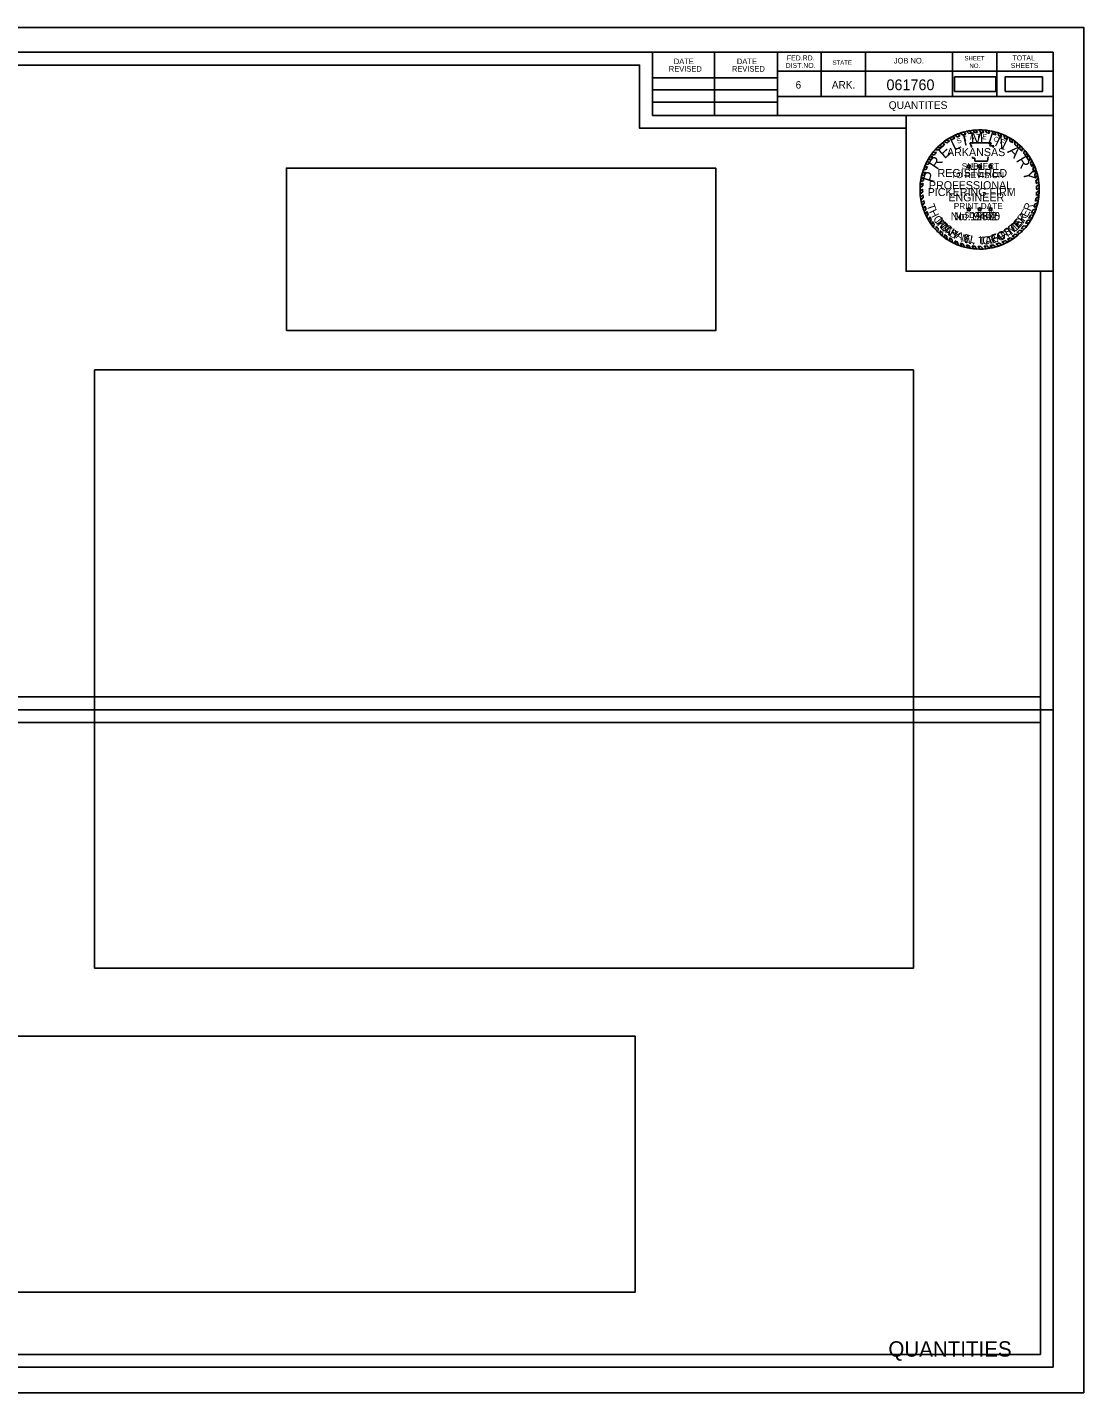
# Model space of a CAD drawing. Extents: x 365 to 1553, y -4 to 209.
# Drawn here: x 907 to 1072.1, y -4 to 209.4 of the extents above; entities that cross this region are included whole.
import ezdxf

# ---------------------------------------------------------------- set-up
doc = ezdxf.new("R2010")
doc.units = 0
for name, color, linetype in [('Default', 7, 'Continuous'), ('R_Border', 7, 'Continuous'), ('R_Border Notes', 7, 'Continuous'), ('R_Border Plan-Plan', 7, 'Continuous'), ('R_Border Title', 7, 'Continuous'), ('R_No Plot', 7, 'Continuous'), ('STAMP_PE_CRAFTON', 7, 'Continuous'), ('STAMP_PE_FOSTER', 7, 'Continuous'), ('STAMP_PE_SEAL-INFO', 7, 'Continuous'), ('STAMP_PE_TAEGTMEYER', 7, 'Continuous'), ('STAMP_PE_TXT', 7, 'Continuous'), ('STAMP_PRELIMINARY', 7, 'Continuous')]:
    doc.layers.add(name, color=color, linetype=linetype)

msp = doc.modelspace()

# ---------------------------------------------------------------- linework, layer by layer
at = {"layer": 'Default'}
for points in [[(1051.92, 199.3), (1058.36, 199.3), (1058.36, 201.61), (1051.92, 201.61)], [(1059.83, 199.3), (1065.66, 199.3), (1065.66, 201.61), (1059.83, 201.61)], [(947.52, 161.96), (1014.61, 161.96), (1014.61, 187.36), (947.52, 187.36)], [(917.53, 62.36), (1045.5, 62.36), (1045.5, 155.81), (917.53, 155.81)], [(810.62, 11.73), (1002.02, 11.73), (1002.02, 51.71), (810.62, 51.71)]]:
    msp.add_lwpolyline(points, close=True, dxfattribs=at)
at = {"layer": 'R_Border'}
for p, q in [((751.17, 205.46), (1067.35, 205.46)), ((1004.71, 195.58), (1004.71, 205.46)), ((1014.39, 195.58), (1014.39, 205.46)), ((1024.25, 205.46), (1024.25, 195.58)), ((1031.09, 205.46), (1031.09, 198.52)), ((1038.03, 205.46), (1038.03, 198.52)), ((1051.61, 205.46), (1051.61, 198.52)), ((1058.55, 205.46), (1058.55, 198.52)), ((1067.35, 0), (1067.35, 205.46)), ((1004.71, 201.44), (1024.25, 201.44)), ((1067.35, 202.52), (1024.25, 202.52)), ((1067.35, 202.54), (1067.35, 202.54)), ((1004.71, 199.58), (1024.25, 199.58)), ((1067.35, 198.52), (1024.25, 198.52)), ((1027.21, 198.52), (1067.35, 198.52)), ((1004.71, 197.64), (1024.25, 197.64)), ((1067.35, 195.58), (1004.71, 195.58)), ((1067.35, 0), (751.17, 0))]:
    msp.add_line(p, q, dxfattribs=at)
at = {"layer": 'R_Border Plan-Plan'}
msp.add_line((751.17, 102.73), (1067.35, 102.73), dxfattribs=at)
at = {"layer": 'R_No Plot'}
for points in [[(738.77, 209.35), (1072.11, 209.35), (1072.11, -3.98), (738.77, -3.98)], [(1065.35, 104.73), (753.17, 104.73), (753.17, 203.46), (1002.71, 203.46), (1002.71, 193.58), (1020.25, 193.58), (1044.35, 193.58), (1044.35, 171.25), (1065.35, 171.25)], [(753.17, 203.46), (1002.71, 203.46), (1002.71, 193.58), (1020.25, 193.58), (1044.35, 193.58), (1044.35, 171.25), (1065.35, 171.25), (1065.35, 2), (753.17, 2)], [(1044.35, 195.58), (1067.35, 195.58), (1067.35, 171.25), (1044.35, 171.25)], [(753.17, 100.73), (1065.35, 100.73), (1065.35, 2), (753.17, 2)]]:
    msp.add_lwpolyline(points, close=True, dxfattribs=at)
at = {"layer": 'STAMP_PE_SEAL-INFO'}
for p, q in [((1051.08, 192.03), (1051.51, 191.81)), ((1051.53, 192.28), (1051.99, 192.06)), ((1051.96, 192.49), (1052.35, 192.22)), ((1052.47, 192.71), (1052.76, 192.38)), ((1052.81, 192.84), (1053.19, 192.53)), ((1053.4, 193.02), (1053.69, 192.67)), ((1053.79, 193.11), (1054.15, 192.77)), ((1054.27, 193.21), (1054.57, 192.84)), ((1054.79, 193.28), (1055.07, 192.9)), ((1055.53, 192.93), (1055.21, 193.32)), ((1056.02, 192.93), (1055.75, 193.34)), ((1056.48, 192.91), (1056.22, 193.34)), ((1056.99, 192.86), (1056.7, 193.31)), ((1057.41, 192.8), (1057.16, 193.25)), ((1057.98, 192.68), (1057.8, 193.14)), ((1058.38, 192.57), (1058.22, 193.04)), ((1058.83, 192.42), (1058.69, 192.9)), ((1059.25, 192.26), (1059.1, 192.76)), ((1059.71, 192.06), (1059.61, 192.56)), ((1060.15, 191.83), (1060.07, 192.34)), ((1060.54, 191.6), (1060.5, 192.1)), ((1048.89, 190.22), (1049.41, 190.19)), ((1049.22, 190.57), (1049.76, 190.53)), ((1049.55, 190.89), (1050.01, 190.75)), ((1049.9, 191.19), (1050.42, 191.09)), ((1050.27, 191.52), (1050.73, 191.31)), ((1050.69, 191.79), (1051.13, 191.58)), ((1054.33, 191.31), (1057.67, 191.31)), ((1054.45, 191.01), (1054.33, 191.31)), ((1054.55, 190.71), (1054.45, 191.01)), ((1054.56, 190.59), (1054.55, 190.71)), ((1057.67, 191.31), (1057.45, 190.82)), ((1057.45, 190.82), (1058.08, 190.82)), ((1058.08, 190.82), (1057.93, 190.59)), ((1060.98, 191.32), (1060.95, 191.83)), ((1061.34, 191.05), (1061.37, 191.54)), ((1061.78, 190.68), (1061.8, 191.2)), ((1062.1, 190.39), (1062.17, 190.88)), ((1062.46, 190.01), (1062.52, 190.54)), ((1062.73, 189.7), (1062.87, 190.17)), ((1047.37, 187.89), (1047.87, 187.99)), ((1047.56, 188.27), (1048.06, 188.34)), ((1047.79, 188.7), (1048.28, 188.72)), ((1048.03, 189.1), (1048.55, 189.13)), ((1048.27, 189.44), (1048.77, 189.44)), ((1048.55, 189.81), (1049.1, 189.83)), ((1054.75, 188.89), (1054.72, 189.1)), ((1055.07, 188.89), (1054.75, 188.89)), ((1055.07, 188.46), (1055.07, 188.89)), ((1057.09, 188.46), (1055.07, 188.46)), ((1057.11, 188.79), (1057.09, 188.46)), ((1057.19, 189.1), (1057.11, 188.79)), ((1063.05, 189.28), (1063.19, 189.78)), ((1063.27, 188.96), (1063.45, 189.43)), ((1063.58, 188.47), (1063.76, 188.96)), ((1063.78, 188.1), (1064.01, 188.54)), ((1064.01, 187.62), (1064.24, 188.1)), ((1047.14, 185.89), (1046.67, 185.64)), ((1046.77, 186.14), (1047.24, 186.33)), ((1046.88, 186.54), (1047.36, 186.71)), ((1047.04, 187.05), (1047.52, 187.18)), ((1047.19, 187.45), (1047.69, 187.6)), ((1064.15, 187.28), (1064.42, 187.71)), ((1064.35, 186.73), (1064.62, 187.2)), ((1064.45, 186.37), (1064.75, 186.82)), ((1064.59, 185.81), (1064.91, 186.25)), ((1064.66, 185.43), (1065.01, 185.78)), ((1046.96, 184.57), (1046.54, 184.31)), ((1046.94, 184.08), (1046.54, 183.74)), ((1046.99, 185), (1046.56, 184.71)), ((1046.95, 183.67), (1046.56, 183.35)), ((1047.05, 185.43), (1046.61, 185.21)), ((1064.72, 184.92), (1065.1, 185.25)), ((1064.75, 184.5), (1065.15, 184.79)), ((1064.76, 183.58), (1065.18, 183.85)), ((1064.77, 183.98), (1065.17, 184.3)), ((1046.98, 183.18), (1046.61, 182.82)), ((1047.03, 182.75), (1046.68, 182.37)), ((1047.11, 182.29), (1046.77, 181.92)), ((1047.2, 181.87), (1046.89, 181.45)), ((1047.33, 181.42), (1047.03, 181)), ((1064.32, 181.24), (1064.81, 181.44)), ((1064.47, 181.73), (1064.94, 181.93)), ((1064.58, 182.18), (1065.03, 182.38)), ((1064.67, 182.68), (1065.11, 182.9)), ((1064.72, 183.07), (1065.15, 183.33)), ((1047.47, 181), (1047.19, 180.59)), ((1047.64, 180.57), (1047.37, 180.15)), ((1047.81, 180.19), (1047.58, 179.73)), ((1048.04, 179.73), (1047.85, 179.24)), ((1048.28, 179.33), (1048.09, 178.86)), ((1063.37, 179.23), (1063.84, 179.22)), ((1063.54, 179.51), (1064.04, 179.56)), ((1063.81, 180), (1064.3, 180.07)), ((1063.97, 180.34), (1064.46, 180.44)), ((1064.19, 180.86), (1064.67, 180.99)), ((1048.48, 179.01), (1048.37, 178.46)), ((1048.76, 178.62), (1048.66, 178.09)), ((1049.07, 178.25), (1048.98, 177.73)), ((1049.37, 177.91), (1049.31, 177.39)), ((1049.69, 177.58), (1049.66, 177.05)), ((1050.03, 177.27), (1050.03, 176.74)), ((1061.68, 177.27), (1062.15, 177.14)), ((1062.08, 177.64), (1062.52, 177.51)), ((1062.34, 177.9), (1062.81, 177.82)), ((1062.72, 178.34), (1063.18, 178.26)), ((1063.03, 178.73), (1063.53, 178.73)), ((1050.39, 176.98), (1050.41, 176.45)), ((1050.73, 176.73), (1050.77, 176.21)), ((1051.16, 176.45), (1051.22, 175.93)), ((1051.51, 176.24), (1051.6, 175.73)), ((1051.99, 175.99), (1052.15, 175.47)), ((1052.36, 175.82), (1052.54, 175.31)), ((1052.86, 175.63), (1053.07, 175.13)), ((1053.27, 175.49), (1053.49, 175)), ((1053.77, 175.36), (1053.99, 174.89)), ((1054.17, 175.27), (1054.42, 174.81)), ((1054.67, 175.19), (1054.91, 174.75)), ((1055.11, 175.14), (1055.38, 174.71)), ((1055.59, 175.11), (1055.9, 174.7)), ((1056.05, 175.11), (1056.4, 174.72)), ((1056.57, 175.14), (1056.9, 174.76)), ((1057.01, 175.18), (1057.38, 174.83)), ((1057.45, 175.25), (1057.84, 174.91)), ((1057.95, 175.36), (1058.33, 175.03)), ((1058.41, 175.48), (1058.82, 175.19)), ((1058.9, 175.65), (1059.34, 175.38)), ((1059.32, 175.81), (1059.74, 175.55)), ((1059.78, 176.02), (1060.26, 175.81)), ((1060.19, 176.23), (1060.6, 176)), ((1060.6, 176.48), (1061.05, 176.28)), ((1060.94, 176.71), (1061.38, 176.52)), ((1061.4, 177.05), (1061.87, 176.9))]:
    msp.add_line(p, q, dxfattribs=at)
for radius, start, end in [(9.32, 117.6544, 120.8099), (8.91, 115.6869, 119.1583), (9.32, 111.3124, 114.7026), (8.91, 110.3086, 113.1659), (9.32, 105.2339, 109.0352), (8.91, 104.0352, 107.3615), (9.32, 99.7525, 102.7765), (8.91, 98.258, 101.0329), (9.32, 93.9381, 96.5517), (8.91, 92.1102, 95.0367), (9.32, 87.7298, 90.6707), (8.91, 85.9628, 88.9097), (9.32, 81.9732, 84.8236), (8.91, 79.9264, 82.696), (9.32, 75.3125, 77.9426), (8.91, 73.5575, 76.2314), (9.32, 69.6061, 72.3058), (8.91, 67.6248, 70.504), (9.32, 63.1329, 66.2704), (8.91, 61.1558, 64.3784), (9.32, 56.9003, 60.0942), (9.32, 135.4021, 138.3031), (8.91, 133.1331, 136.2562), (9.32, 129.7326, 132.5376), (8.91, 127.5297, 130.9683), (9.32, 123.6199, 126.5906), (8.91, 121.9746, 125.11), (8.91, 54.9238, 58.2702), (8.91, 48.3016, 52.0395), (9.32, 50.3492, 53.7159), (8.91, 42.2212, 45.5512), (9.32, 44.3405, 47.3929), (9.32, 38.1247, 41.2316), (9.32, 152.864, 155.5189), (9.32, 147.0072, 149.899), (8.91, 151.0315, 153.573), (9.32, 141.6056, 144.4486), (8.91, 145.0197, 148.2104), (8.91, 139.301, 142.5873), (8.91, 36.135, 39.5311), (8.91, 29.9032, 33.6645), (9.32, 31.9614, 35.4294), (8.91, 23.7732, 27.2211), (9.32, 25.9391, 29.0125), (9.32, 170.0003, 172.6878), (9.32, 164.3068, 166.894), (9.32, 158.4077, 161.0701), (8.91, 167.9048, 170.9039), (8.91, 162.4331, 165.0013), (8.91, 156.3402, 159.2319), (8.91, 17.6802, 21.4251), (9.32, 19.9538, 23.3141), (8.91, 11.5444, 15.2364), (9.32, 13.8421, 17.4447), (9.32, 7.5852, 10.8621), (9.32, 175.7409, 178.2066), (9.32, 181.7251, 184.1626), (8.91, 179.6454, 182.2633), (8.91, 173.73, 176.4734), (8.91, 5.7599, 9.0606), (8.91, 353.8632, 357.1274), (8.91, 359.7329, 3.0639), (9.32, 1.7215, 4.7268), (9.32, 355.7156, 358.9569), (9.32, 187.4204, 190.1927), (9.32, 193.0369, 195.9973), (8.91, 185.4539, 188.234), (8.91, 191.2274, 193.9858), (8.91, 196.9675, 199.8353), (8.91, 341.777, 345.0925), (8.91, 348.0778, 351.3435), (9.32, 343.8925, 347.035), (9.32, 349.8305, 353.0885), (9.32, 198.8967, 201.6281), (9.32, 204.5479, 207.4328), (8.91, 202.7761, 205.4791), (9.32, 210.8636, 213.6571), (8.91, 208.7883, 211.7934), (8.91, 323.5851, 327.4407), (9.32, 325.4405, 328.9872), (8.91, 329.5549, 333.2076), (8.91, 335.6038, 339.1858), (9.32, 331.4037, 334.9332), (9.32, 337.3837, 340.9933), (9.32, 216.6115, 219.491), (8.91, 214.1838, 217.2747), (9.32, 222.48, 225.3801), (8.91, 220.3909, 223.3056), (8.91, 226.2494, 229.2407), (8.91, 310.7744, 314.3161), (9.32, 312.4518, 315.6633), (8.91, 316.6531, 320.3711), (9.32, 318.2846, 321.8043), (9.32, 228.3665, 231.348), (8.91, 232.229, 234.9336), (9.32, 234.295, 236.9452), (8.91, 238.2223, 240.8353), (9.32, 240.1977, 242.8613), (8.91, 244.3204, 246.9486), (9.32, 246.576, 249.1558), (8.91, 250.3491, 253.1216), (9.32, 252.5967, 255.3252), (8.91, 256.505, 259.1192), (8.91, 262.3783, 265.2012), (8.91, 268.3215, 271.277), (8.91, 274.6157, 277.4486), (8.91, 280.3459, 283.5814), (9.32, 282.3199, 285.3702), (8.91, 286.6423, 289.9783), (9.32, 288.5709, 291.9733), (8.91, 292.8745, 296.1185), (9.32, 294.6481, 298.2166), (8.91, 299.0768, 302.1724), (9.32, 300.621, 303.8703), (8.91, 304.823, 308.5143), (9.32, 306.3721, 310.208), (9.32, 258.4433, 261.1398), (9.32, 264.1978, 267.1009), (9.32, 270.2548, 273.3361), (9.32, 276.4239, 279.4357)]:
    msp.add_arc((1055.85, 184.02), radius, start, end, dxfattribs=at)
at = {"layer": 'STAMP_PE_TXT'}
for p, q in [((1054.03, 187.59), (1053.84, 187.74)), ((1053.84, 187.74), (1054.08, 187.74)), ((1054.08, 187.74), (1054.16, 187.97)), ((1054.16, 187.97), (1054.23, 187.74)), ((1054.23, 187.74), (1054.48, 187.74)), ((1054.48, 187.74), (1054.28, 187.59)), ((1055.73, 187.59), (1055.53, 187.74)), ((1055.53, 187.74), (1055.78, 187.74)), ((1055.78, 187.74), (1055.85, 187.97)), ((1055.85, 187.97), (1055.93, 187.74)), ((1055.93, 187.74), (1056.18, 187.74)), ((1056.18, 187.74), (1055.98, 187.59)), ((1057.43, 187.59), (1057.23, 187.74)), ((1057.23, 187.74), (1057.48, 187.74)), ((1057.48, 187.74), (1057.55, 187.97)), ((1057.55, 187.97), (1057.63, 187.74)), ((1057.63, 187.74), (1057.87, 187.74)), ((1057.87, 187.74), (1057.67, 187.59)), ((1053.96, 187.36), (1054.03, 187.59)), ((1054.16, 187.5), (1053.96, 187.36)), ((1054.35, 187.36), (1054.16, 187.5)), ((1054.28, 187.59), (1054.35, 187.36)), ((1055.66, 187.36), (1055.73, 187.59)), ((1055.85, 187.5), (1055.66, 187.36)), ((1056.05, 187.36), (1055.85, 187.5)), ((1055.98, 187.59), (1056.05, 187.36)), ((1057.35, 187.36), (1057.43, 187.59)), ((1057.55, 187.5), (1057.35, 187.36)), ((1057.75, 187.36), (1057.55, 187.5)), ((1057.67, 187.59), (1057.75, 187.36)), ((1054.03, 180.89), (1053.84, 181.03)), ((1053.84, 181.03), (1054.08, 181.03)), ((1053.96, 180.65), (1054.03, 180.89)), ((1054.16, 180.8), (1053.96, 180.65)), ((1054.08, 181.03), (1054.16, 181.26)), ((1054.16, 181.26), (1054.23, 181.03)), ((1054.35, 180.65), (1054.16, 180.8)), ((1054.23, 181.03), (1054.48, 181.03)), ((1054.48, 181.03), (1054.28, 180.89)), ((1054.28, 180.89), (1054.35, 180.65)), ((1055.73, 180.89), (1055.53, 181.03)), ((1055.53, 181.03), (1055.78, 181.03)), ((1055.66, 180.65), (1055.73, 180.89)), ((1055.85, 180.8), (1055.66, 180.65)), ((1055.78, 181.03), (1055.85, 181.26)), ((1055.85, 181.26), (1055.93, 181.03)), ((1056.05, 180.65), (1055.85, 180.8)), ((1055.93, 181.03), (1056.18, 181.03)), ((1056.18, 181.03), (1055.98, 180.89)), ((1055.98, 180.89), (1056.05, 180.65)), ((1057.43, 180.89), (1057.23, 181.03)), ((1057.23, 181.03), (1057.48, 181.03)), ((1057.35, 180.65), (1057.43, 180.89)), ((1057.55, 180.8), (1057.35, 180.65)), ((1057.48, 181.03), (1057.55, 181.26)), ((1057.55, 181.26), (1057.63, 181.03)), ((1057.75, 180.65), (1057.55, 180.8)), ((1057.63, 181.03), (1057.87, 181.03)), ((1057.87, 181.03), (1057.67, 180.89)), ((1057.67, 180.89), (1057.75, 180.65))]:
    msp.add_line(p, q, dxfattribs=at)
at = {"layer": 'STAMP_PRELIMINARY'}
msp.add_circle((1055.85, 184.02), 9.32, dxfattribs=at)

# ---------------------------------------------------------------- texts
at = {"layer": 'R_Border'}
for s, height, p in [('FED.RD.', 0.782, (1025.73, 204.18)), ('SHEET', 0.684, (1053.47, 204.18)), ('TOTAL', 0.782, (1060.99, 204.18)), ('REVISED', 0.879, (1007.27, 202.42)), ('DATE', 0.879, (1008.05, 203.6)), ('REVISED', 0.879, (1017.13, 202.42)), ('DATE', 0.879, (1017.91, 203.6)), ('DIST.NO.', 0.782, (1025.53, 203)), ('STATE', 0.684, (1032.85, 203.5)), ('JOB NO.', 0.879, (1042.43, 203.7)), ('NO.', 0.684, (1054.25, 203)), ('SHEETS', 0.782, (1060.71, 203)), ('6', 1.17, (1027.09, 199.78)), ('ARK.', 1.172, (1032.75, 199.78))]:
    msp.add_text(s, height=height, dxfattribs=at).set_placement(p)
at = {"layer": 'R_Border Notes'}
for s, height, p in [('061760', 1.68, (1041.29, 199.53)), ('QUANTITES', 1.2, (1041.63, 196.6))]:
    msp.add_text(s, height=height, dxfattribs=at).set_placement(p)
at = {"layer": 'R_Border Title'}
msp.add_text('QUANTITIES', height=2.4, dxfattribs=at).set_placement((1041.59, 1.65))
at = {"layer": 'STAMP_PE_CRAFTON'}
for s, rotation, p in [('T', 310.7442, (1048.82, 178.92)), ('N', 49.2411, (1062.14, 178.04)), ('O', 317.6422, (1049.49, 178.11)), ('N', 324.4537, (1050.33, 177.32)), ('Y', 331.1686, (1051.37, 176.61)), ('A', 20.5125, (1058.53, 175.78)), ('F', 28.7821, (1059.52, 176.15)), ('T', 34.1136, (1060.43, 176.66)), ('O', 41.8391, (1061.29, 177.26)), ('N', 347.4752, (1053.42, 175.69)), ('.', 356.8926, (1054.65, 175.41)), ('C', 6.0117, (1056.33, 175.36)), ('R', 14.8189, (1057.42, 175.48))]:
    msp.add_text(s, height=1.25, rotation=rotation, dxfattribs=at).set_placement(p)
msp.add_text('No. 12370', height=1.25, dxfattribs=at).set_placement((1051.32, 179.22))
at = {"layer": 'STAMP_PE_FOSTER'}
for s, rotation, p in [('M', 308.339, (1048.97, 179.04)), ('E', 46.9613, (1061.85, 178.01)), ('R', 54.5031, (1062.58, 178.83)), ('I', 314.1842, (1049.77, 178.11)), ('C', 319.8733, (1050.12, 177.75)), ('H', 327.7235, (1051.05, 177.02)), ('A', 335.7276, (1052.03, 176.44)), ('E', 343.5779, (1053.17, 175.97)), ('F', 15.8691, (1057.89, 175.78)), ('O', 23.719, (1058.93, 176.1)), ('S', 31.7234, (1060.04, 176.63)), ('T', 39.4194, (1061, 177.26)), ('L', 350.8115, (1054.23, 175.69)), ('L', 1.2666, (1055.77, 175.53)), ('.', 6.8035, (1056.81, 175.59))]:
    msp.add_text(s, height=1.2, rotation=rotation, dxfattribs=at).set_placement(p)
msp.add_text('No. 9402', height=1.25, dxfattribs=at).set_placement((1051.84, 179.22))
at = {"layer": 'STAMP_PE_TAEGTMEYER'}
for s, rotation, p in [('T', 289.646, (1047.55, 181.53)), ('R', 69.57, (1063.8, 180.54)), ('H', 296.7339, (1047.91, 180.55)), ('O', 303.7708, (1048.5, 179.44)), ('M', 314.2033, (1049.16, 178.49)), ('E', 46.8094, (1061.89, 177.8)), ('Y', 53.9986, (1062.63, 178.61)), ('E', 63.0984, (1063.3, 179.56)), ('A', 321.0594, (1050.12, 177.52)), ('S', 327.8239, (1050.94, 176.88)), ('G', 23.3052, (1058.85, 175.88)), ('T', 31.466, (1059.95, 176.38)), ('M', 39.3, (1060.85, 176.92)), ('N', 344.2727, (1052.84, 175.87)), ('.', 350.6464, (1054.05, 175.54)), ('T', 3.0061, (1055.72, 175.34)), ('A', 8.9826, (1056.77, 175.4)), ('E', 17.6836, (1057.8, 175.55))]:
    msp.add_text(s, height=1.25, rotation=rotation, dxfattribs=at).set_placement(p)
msp.add_text('No. 19605', height=1.25, dxfattribs=at).set_placement((1051.32, 179.22))
at = {"layer": 'STAMP_PE_TXT'}
for s, rotation, p in [('S', 23.5541, (1052.45, 191.13)), ('T', 16.311, (1053.38, 191.5)), ('A', 9.0679, (1054.34, 191.75)), ('T', 1.8248, (1055.32, 191.88)), ('E', 355.2002, (1056.23, 191.89)), ('O', 342.2506, (1057.96, 191.61)), ('F', 335.0075, (1058.93, 191.27))]:
    msp.add_text(s, height=0.781, rotation=rotation, dxfattribs=at).set_placement(p)
for s, p in [('ARKANSAS', (1050.75, 189.23)), ('REGISTERED', (1049.27, 185.96)), ('PROFESSIONAL', (1047.92, 184.06)), ('ENGINEER', (1050.96, 182.16))]:
    msp.add_text(s, height=1.25, dxfattribs=at).set_placement(p)
at = {"layer": 'STAMP_PRELIMINARY'}
for s, rotation, p in [('I', 12.5248, (1053.39, 190.81)), ('M', 3.1074, (1054.49, 191.12)), ('I', 342.3164, (1056.96, 191.19)), ('N', 333.9382, (1058.07, 190.91)), ('E', 42.3578, (1050.38, 188.72)), ('L', 25.513, (1051.86, 190.05)), ('A', 315.6579, (1060.1, 189.89)), ('R', 56.2292, (1049.22, 186.99)), ('R', 301.3831, (1061.47, 188.57)), ('P', 73.913, (1048.68, 184.96)), ('Y', 283.2593, (1062.56, 186.79))]:
    msp.add_text(s, height=1.8, rotation=rotation, dxfattribs=at).set_placement(p)
for s, height, p in [('SUBJECT', 0.96, (1053.05, 187.17)), ('TO REVISION', 0.96, (1051.39, 185.79)), ('PICKERING FIRM', 1.25, (1047.73, 182.99)), ('PRINT DATE', 0.96, (1051.81, 180.94)), ('$DATE$', 0.96, (1053.49, 179.55))]:
    msp.add_text(s, height=height, dxfattribs=at).set_placement(p)

doc.saveas('drawing.dxf')
